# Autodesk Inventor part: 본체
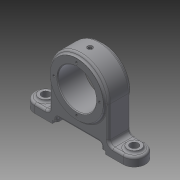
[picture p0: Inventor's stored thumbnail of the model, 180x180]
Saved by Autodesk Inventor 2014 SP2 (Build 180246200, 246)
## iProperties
Created: 2019-05
Part Number: 본체
Material: Generic
Document SubType Name: Modeling
Designer: gs
Density: 1 g/cm^3
Appearance: Default
Author: gs
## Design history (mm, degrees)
sketch "스케치1"
  geometry: L1 (0, 18)-(0, -18); L2 (0, 18)-(36, 18); L3 (36, 18)-(36, 15); L4 (36, 15)-(40, 15); L5 (40, 15)-(40, -15); L6 (40, -15)-(36, -15); L7 (36, -15)-(36, -18); L8 (36, -18)-(0, -18); 2 further points
  constraints: 16 end point, 3 perpendicular, 2 parallel, 1 coincident, 1 collinear, 1 midpoint, 1 vertical
  dimensions: "d0" = 36 distance of L1.start L1.end; "d2" = 36 distance of L1.start L2.end; "d3" = 3 distance of L2.end L3.end; "d4" = 4 distance of L3.end L4.end; "d5" = 30 distance of L4.end L5.end; "d6" = 4 distance of L5.end L6.end; "d7" = 3 distance of L6.end L7.end
revolve "회전1" sketch "스케치1" stored, may be unused: angle "d8" = 90 deg
sketch "스케치2"
  geometry: C1 r 36 at (0, 0) reference; 1 further point
  constraints: 1 coincident
hole "구멍1" sketch "스케치2" at (0, 0) diameter "d9" = 52; stored, may be unused: countersink angle "d13" = 90 deg, drill point angle "d15" = 118 deg; dims "d10" = 6, "d11" = 4, "d12" = 2, "d14" = 8
sketch "스케치3"
  geometry: C1 r 26 at (0, 0) reference; 1 further point
  constraints: 1 vertical alignment
  dimensions: "d16" = 31 distance of C1.centre point (0, 31)
hole "구멍2" sketch "스케치3" at (0, 31) diameter "d17" = 3.242; stored, may be unused: countersink angle "d21" = 90 deg, drill point angle "d23" = 118 deg; dims "d18" = 6, "d19" = 4, "d20" = 2, "d22" = 8
node "작업 평면1"
sketch "스케치4"
  geometry: 2 further points
  constraints: 1 coincident
hole "구멍3" sketch "스케치4" at (0, 0) diameter "d28" = 4.917; stored, may be unused: countersink angle "d32" = 90 deg, drill point angle "d34" = 118 deg; dims "d29" = 8, "d30" = 7, "d31" = 1, "d33" = 10
node "작업 평면2"
sketch "스케치5"
  geometry: 2 further points
  constraints: 1 coincident
hole "구멍4" sketch "스케치5" at (0, 0) diameter "d36" = 2; stored, may be unused: countersink angle "d40" = 90 deg, drill point angle "d42" = 118 deg; dims "d37" = 8, "d38" = 7, "d39" = 1, "d41" = 10
sketch "스케치6"
  geometry: C1 r 1.621 at (0, 31) reference; 2 further points
  constraints: 2 vertical alignment, 1 other
hole "구멍5" sketch "스케치6" at (0, 26) diameter "d43" = 3; stored, may be unused: countersink angle "d47" = 90 deg, drill point angle "d49" = 118 deg; dims "d44" = 8, "d45" = 7, "d46" = 1, "d48" = 10
chamfer "모따기1" distance "d50" = 1; stored, may be unused: second distance "d51" = 2, angle "d52" = 45 deg
node "작업 평면3"
sketch "스케치7"
  geometry: L1 (-40, 0)-(-40, -48); L2 (-40, -48)-(-75, -48); L3 (-75, -48)-(-75, -60); L4 (-75, -60)-(-36, -60); L5 (-36, -60)-(-36, -56); L6 (-36, -56)-(-30, -56); L7 (-30, -56)-(-30, -50); L8 (-30, -50)-(30, -50); L9 (30, -50)-(30, -56); L10 (30, -56)-(36, -56); L11 (36, -56)-(36, -60); L12 (36, -60)-(75, -60); L13 (75, -60)-(75, -48); L14 (75, -48)-(40, -48); L15 (40, -48)-(40, 0); A1 r 40 centre (0, 0) between (-40, 0) and (40, 0) reference; 1 further point
  constraints: 30 end point, 11 parallel, 7 equal length, 7 horizontal alignment, 3 perpendicular, 2 point on circle, 1 tangent, 1 vertical
  dimensions: "d55" = 10 distance from line of L8 L4.end; "d56" = 4 distance of L4.end L5.end; "d57" = 12 distance of L2.end L3.end; "d58" = 72 distance of L11.end L4.end; "d59" = 60 distance of L9.end L6.end; "d62" = 60 vertical distance of L3.end L1.start; "d64" = 75 horizontal distance of L13.end point (0, 0)
extrude "돌출1" join sketch "스케치7" stored distance "d66" = 30; taper "d67" = 0 deg
fillet "모깎기1" dims "d68" = 15
fillet "모깎기2" dims "d69" = 6
fillet "모깎기3" dims "d70" = 3
sketch "스케치9"
  geometry: L1 (14, 0)-(0, 0) reference; L2 (0, 24)-(14, 24) reference; L3 (14, 0)-(14, 24) reference; L4 (99.292, -3)-(20.708, -3) reference; L5 (106, 0)-(106, 24) reference; L6 (20.708, 27)-(99.292, 27) reference; L7 (120, 0)-(106, 0) reference; L8 (106, 24)-(120, 24) reference; C1 r 9 at (0, 12); A1 r 12 centre (0, 12) between (0, 24) and (0, 0) reference; A2 r 12 centre (120, 12) between (120, 0) and (120, 24) reference; A3 r 15 centre (0, 12) between (0, 27) and (0, -3) reference; A4 r 15 centre (120, 12) between (120, -3) and (120, 27) reference; 1 further point
  constraints: 1 centre point, 1 horizontal alignment, 4 other
  dimensions: "d79" = 18 diameter of C1; "d80" = 60 distance of point (60, 12) C1.centre
extrude "돌출2" join sketch "스케치9" distance "d82" = 3; taper "d83" = 0 deg
sketch "스케치10"
  geometry: C1 r 9 at (0, 0) reference; 2 further points
  constraints: 1 coincident
hole "구멍7" sketch "스케치10" at (0, 0) diameter "d84" = 11; stored, may be unused: countersink angle "d88" = 90 deg, drill point angle "d90" = 118 deg; dims "d85" = 8, "d86" = 7, "d87" = 1, "d89" = 10
fillet "모깎기4" dims "d91" = 3
sketch "스케치11"
  geometry: C1 r 9 at (14, 12); A1 r 12 centre (14, 12) between (14, 0) and (14, 24) reference; 1 further point
  constraints: 1 centre point, 1 coincident
  dimensions: "d92" = 18 diameter of C1
extrude "돌출3" join sketch "스케치11" distance "d93" = 3; taper "d94" = 0 deg
sketch "스케치12"
  geometry: C1 r 9 at (0, 0) reference; 2 further points
  constraints: 1 coincident
hole "구멍8" sketch "스케치12" at (0, 0) diameter "d95" = 11; stored, may be unused: countersink angle "d99" = 90 deg, drill point angle "d101" = 118 deg; dims "d96" = 8, "d97" = 7, "d98" = 1, "d100" = 10
fillet "모깎기5" dims "d102" = 3
fillet "모깎기6" dims "d103" = 3
fillet "모깎기7" dims "d104" = 3
node "솔리드1"
pattern_circular "원형 패턴1" dims angle "d25" = 360 deg
mirror "대칭1"
node "절단 모서리 투영1"
other parameters: "d35" = 26, "d53" = 0
